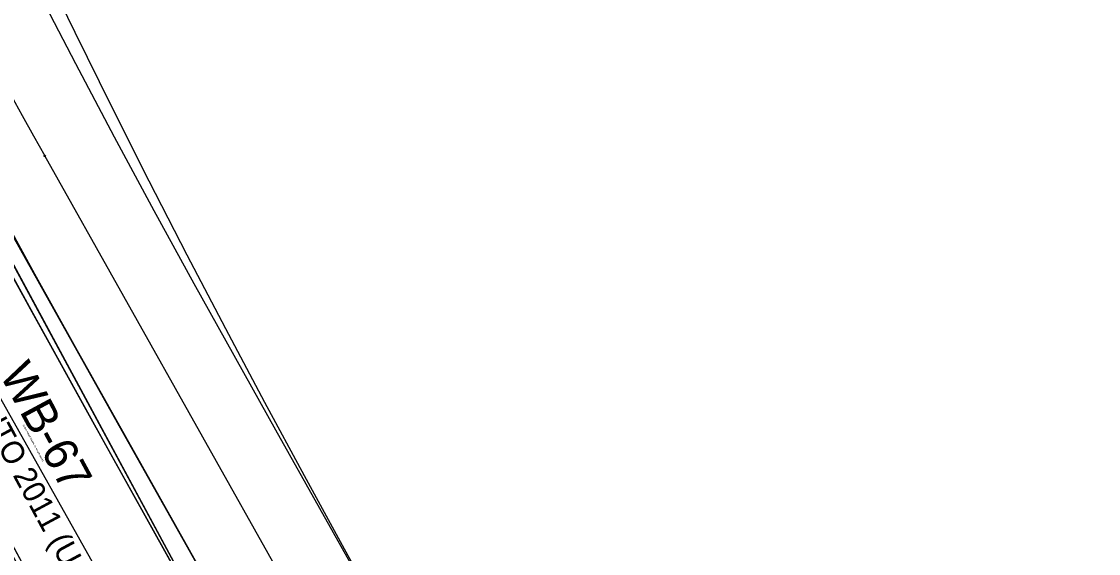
# Model space of a CAD drawing. Extents: x 1639988 to 1641860, y 841974 to 844187.
# Drawn here: x 1640568.3 to 1640636.6, y 843404.6 to 843438.4 of the extents above; entities that cross this region are included whole.
import ezdxf

# ---------------------------------------------------------------- set-up
doc = ezdxf.new("R2010")
doc.units = 0
for name, color, linetype in [('Scratch_Level_1', 7, 'Continuous'), ('Scratch_Level_2', 7, 'Continuous'), ('Scratch_Level_3', 7, 'Continuous'), ('Scratch_Level_4', 7, 'Continuous'), ('Scratch_Level_5', 7, 'Continuous'), ('Scratch_Level_6', 7, 'Continuous')]:
    doc.layers.add(name, color=color, linetype=linetype)

msp = doc.modelspace()

# ---------------------------------------------------------------- linework, layer by layer
at = {"layer": 'Scratch_Level_1'}
for p, q in [((1640598.915, 843377.886), (1640569.74, 843429.881)), ((1640561.019, 843424.987), (1640589.875, 843373.561))]:
    msp.add_line(p, q, dxfattribs=at)
for points in [[(1640557.303, 843442.315), (1640585.531, 843389.964), (1640585.474, 843389.635), (1640595.318, 843372.019), (1640588.329, 843368.125), (1640578.269, 843386.026), (1640578.051, 843385.927), (1640567.623, 843404.617), (1640561.145, 843416.327), (1640558.494, 843420.979), (1640555.889, 843425.657), (1640554.452, 843428.305), (1640561.33, 843432.392), (1640554.136, 843428.893), (1640551.649, 843433.615), (1640549.228, 843438.375), (1640546.875, 843443.171)], [(1640569.35, 843442.491), (1640571.641, 843437.743), (1640573.976, 843433.013), (1640576.351, 843428.298), (1640578.765, 843423.598), (1640581.214, 843418.911), (1640583.696, 843414.235), (1640586.206, 843409.569), (1640588.742, 843404.91), (1640593.874, 843395.608), (1640599.062, 843386.314), (1640636.63, 843319.355), (1640629.218, 843315.196), (1640629.14, 843315.333), (1640629.14, 843315.333)], [(1640629.14, 843315.333), (1640571.712, 843417.686), (1640569.11, 843422.364), (1640566.534, 843427.059), (1640563.994, 843431.777), (1640560.226, 843438.882)], [(1640552.934, 843432.517), (1640552.915, 843432.507), (1640552.949, 843432.445), (1640555.639, 843427.457), (1640578.051, 843385.927), (1640581.791, 843387.945), (1640585.531, 843389.964), (1640563.12, 843431.494), (1640560.428, 843436.481), (1640560.394, 843436.543), (1640560.375, 843436.533)]]:
    msp.add_lwpolyline(points, dxfattribs=at)
msp.add_circle((1640569.74, 843429.881), 0.0417, dxfattribs=at)
msp.add_circle((1640569.74, 843429.881), 0.0417, dxfattribs=at)
msp.add_arc((1640914.217, 843623.17), 395, 195.7144, 209.29724, dxfattribs=at)
at = {"layer": 'Scratch_Level_2'}
for p, q in [((1640598.915, 843377.886), (1640569.74, 843429.881)), ((1640561.019, 843424.987), (1640589.875, 843373.561))]:
    msp.add_line(p, q, dxfattribs=at)
for points in [[(1640557.951, 843441.151), (1640585.531, 843389.961), (1640585.474, 843389.635), (1640595.318, 843372.019), (1640588.329, 843368.125), (1640578.268, 843386.026), (1640578.049, 843385.928), (1640567.621, 843404.618), (1640561.144, 843416.329), (1640558.493, 843420.981), (1640555.888, 843425.659), (1640554.451, 843428.306), (1640561.331, 843432.39), (1640554.135, 843428.895), (1640551.648, 843433.617), (1640549.227, 843438.377), (1640546.874, 843443.173)], [(1640569.35, 843442.491), (1640571.641, 843437.743), (1640573.976, 843433.013), (1640576.351, 843428.298), (1640578.765, 843423.598), (1640581.214, 843418.911), (1640583.696, 843414.235), (1640586.206, 843409.569), (1640588.742, 843404.91), (1640593.874, 843395.608), (1640599.062, 843386.314), (1640636.63, 843319.355), (1640629.218, 843315.196), (1640629.144, 843315.327), (1640629.144, 843315.327)], [(1640629.144, 843315.327), (1640571.712, 843417.686), (1640569.11, 843422.364), (1640566.534, 843427.059), (1640563.994, 843431.777), (1640560.226, 843438.882)], [(1640552.951, 843432.529), (1640552.932, 843432.518), (1640552.966, 843432.456), (1640555.654, 843427.467), (1640578.049, 843385.928), (1640581.79, 843387.945), (1640585.531, 843389.961), (1640563.136, 843431.501), (1640560.446, 843436.489), (1640560.413, 843436.551), (1640560.394, 843436.541)]]:
    msp.add_lwpolyline(points, dxfattribs=at)
msp.add_circle((1640569.74, 843429.881), 0.0417, dxfattribs=at)
msp.add_circle((1640569.74, 843429.881), 0.0417, dxfattribs=at)
msp.add_arc((1640914.217, 843623.17), 395, 195.7144, 209.29724, dxfattribs=at)
at = {"layer": 'Scratch_Level_3'}
for p, q in [((1640598.915, 843377.886), (1640569.74, 843429.881)), ((1640561.019, 843424.987), (1640589.875, 843373.561))]:
    msp.add_line(p, q, dxfattribs=at)
for points in [[(1640556.856, 843443.205), (1640561.886, 843433.823), (1640585.531, 843389.961), (1640585.474, 843389.635), (1640595.318, 843372.019), (1640588.331, 843368.123), (1640578.268, 843386.026), (1640578.049, 843385.928), (1640567.621, 843404.618), (1640561.144, 843416.329), (1640558.493, 843420.981), (1640555.888, 843425.659), (1640554.451, 843428.306), (1640561.331, 843432.39), (1640554.135, 843428.895), (1640551.648, 843433.617), (1640549.227, 843438.377), (1640546.874, 843443.174)], [(1640569.35, 843442.491), (1640571.641, 843437.743), (1640573.976, 843433.013), (1640576.351, 843428.298), (1640578.765, 843423.598), (1640581.214, 843418.911), (1640583.696, 843414.235), (1640586.206, 843409.569), (1640588.742, 843404.91), (1640593.874, 843395.608), (1640599.062, 843386.314), (1640636.63, 843319.355), (1640629.218, 843315.196), (1640629.149, 843315.318), (1640629.149, 843315.318)], [(1640629.149, 843315.318), (1640571.712, 843417.686), (1640569.11, 843422.364), (1640566.534, 843427.059), (1640563.994, 843431.777), (1640560.226, 843438.882)], [(1640552.953, 843432.529), (1640552.933, 843432.519), (1640552.967, 843432.457), (1640555.656, 843427.468), (1640578.049, 843385.928), (1640581.79, 843387.945), (1640585.531, 843389.961), (1640563.138, 843431.501), (1640560.448, 843436.49), (1640560.414, 843436.552), (1640560.395, 843436.542)]]:
    msp.add_lwpolyline(points, dxfattribs=at)
msp.add_circle((1640569.74, 843429.881), 0.0417, dxfattribs=at)
msp.add_circle((1640569.74, 843429.881), 0.0417, dxfattribs=at)
msp.add_arc((1640914.217, 843623.17), 395, 195.7144, 209.29724, dxfattribs=at)
at = {"layer": 'Scratch_Level_4'}
for p, q in [((1640598.915, 843377.886), (1640569.74, 843429.881)), ((1640561.019, 843424.987), (1640589.875, 843373.561))]:
    msp.add_line(p, q, dxfattribs=at)
for points in [[(1640558.794, 843438.559), (1640563.861, 843429.211), (1640568.98, 843419.88), (1640574.133, 843410.56), (1640596.995, 843369.516), (1640589.571, 843365.377), (1640573.868, 843393.261), (1640581.129, 843397.688), (1640573.54, 843393.841), (1640559.056, 843419.365), (1640557.759, 843421.699), (1640556.481, 843424.044), (1640555.22, 843426.399), (1640553.978, 843428.764), (1640544.238, 843447.821)], [(1640611.208, 843347.292), (1640590.328, 843384.504), (1640574.652, 843412.392), (1640569.434, 843421.74), (1640561.561, 843435.788), (1640560.271, 843438.147), (1640559.001, 843440.517)], [(1640569.265, 843440.462), (1640571.686, 843435.764), (1640574.153, 843431.085), (1640576.662, 843426.421), (1640579.206, 843421.768), (1640584.378, 843412.479), (1640618.769, 843351.186), (1640611.357, 843347.027), (1640611.208, 843347.292), (1640611.208, 843347.292)]]:
    msp.add_lwpolyline(points, dxfattribs=at)
msp.add_circle((1640569.74, 843429.881), 0.0417, dxfattribs=at)
msp.add_circle((1640569.74, 843429.881), 0.0417, dxfattribs=at)
msp.add_arc((1640914.217, 843623.17), 395, 195.7144, 209.29724, dxfattribs=at)
at = {"layer": 'Scratch_Level_5'}
for p, q in [((1640598.915, 843377.886), (1640569.74, 843429.881)), ((1640561.019, 843424.987), (1640589.875, 843373.561))]:
    msp.add_line(p, q, dxfattribs=at)
for points in [[(1640558.636, 843438.852), (1640563.702, 843429.503), (1640568.819, 843420.171), (1640573.971, 843410.851), (1640596.995, 843369.516), (1640589.571, 843365.377), (1640573.868, 843393.261), (1640581.129, 843397.688), (1640573.54, 843393.841), (1640559.056, 843419.365), (1640557.759, 843421.699), (1640556.481, 843424.044), (1640555.22, 843426.399), (1640553.978, 843428.764), (1640544.238, 843447.821)], [(1640611.214, 843347.281), (1640590.328, 843384.504), (1640574.652, 843412.392), (1640569.434, 843421.74), (1640561.561, 843435.788), (1640560.271, 843438.147), (1640559.001, 843440.517)], [(1640569.265, 843440.462), (1640571.686, 843435.764), (1640574.153, 843431.085), (1640576.662, 843426.421), (1640579.206, 843421.768), (1640584.378, 843412.479), (1640618.769, 843351.186), (1640611.357, 843347.027), (1640611.214, 843347.281), (1640611.214, 843347.281)]]:
    msp.add_lwpolyline(points, dxfattribs=at)
msp.add_circle((1640569.74, 843429.881), 0.0417, dxfattribs=at)
msp.add_circle((1640569.74, 843429.881), 0.0417, dxfattribs=at)
msp.add_arc((1640914.217, 843623.17), 395, 195.7144, 209.29724, dxfattribs=at)
at = {"layer": 'Scratch_Level_6'}
for p, q in [((1640598.915, 843377.886), (1640569.74, 843429.881)), ((1640561.019, 843424.987), (1640589.875, 843373.561))]:
    msp.add_line(p, q, dxfattribs=at)
for points in [[(1640557.068, 843441.778), (1640562.112, 843432.422), (1640567.216, 843423.086), (1640572.358, 843413.763), (1640582.875, 843394.846), (1640596.995, 843369.516), (1640589.571, 843365.377), (1640573.868, 843393.261), (1640581.129, 843397.688), (1640573.54, 843393.841), (1640559.056, 843419.365), (1640557.759, 843421.699), (1640556.481, 843424.044), (1640555.22, 843426.399), (1640553.978, 843428.764), (1640544.238, 843447.821)], [(1640611.238, 843347.239), (1640590.328, 843384.504), (1640574.652, 843412.392), (1640569.434, 843421.74), (1640561.561, 843435.788), (1640560.271, 843438.147), (1640559.001, 843440.517)], [(1640569.265, 843440.462), (1640571.686, 843435.764), (1640574.153, 843431.085), (1640576.662, 843426.421), (1640579.206, 843421.768), (1640584.378, 843412.479), (1640618.769, 843351.186), (1640611.357, 843347.027), (1640611.238, 843347.239), (1640611.238, 843347.239)]]:
    msp.add_lwpolyline(points, dxfattribs=at)
msp.add_circle((1640569.74, 843429.881), 0.0417, dxfattribs=at)
msp.add_circle((1640569.74, 843429.881), 0.0417, dxfattribs=at)
msp.add_arc((1640914.217, 843623.17), 395, 195.7144, 209.29724, dxfattribs=at)

# ---------------------------------------------------------------- texts
at = {"layer": 'Scratch_Level_1'}
for s, height, p in [('AASHTO 2011 (US)', 1.41667, (1640563.738, 843416.91)), ('WB-67', 2.125, (1640566.833, 843416.022)), ('(c) 2019 Transoft Solutions, Inc. All rights reserved.', 0.085, (1640568.346, 843412.771))]:
    msp.add_text(s, height=height, rotation=298.35288, dxfattribs=at).set_placement(p)
at = {"layer": 'Scratch_Level_2'}
for s, height, p in [('AASHTO 2011 (US)', 1.41667, (1640563.748, 843416.917)), ('WB-67', 2.125, (1640566.843, 843416.028)), ('(c) 2019 Transoft Solutions, Inc. All rights reserved.', 0.085, (1640568.355, 843412.775))]:
    msp.add_text(s, height=height, rotation=298.32975, dxfattribs=at).set_placement(p)
at = {"layer": 'Scratch_Level_3'}
for s, height, p in [('AASHTO 2011 (US)', 1.41667, (1640563.749, 843416.918)), ('WB-67', 2.125, (1640566.844, 843416.028)), ('(c) 2019 Transoft Solutions, Inc. All rights reserved.', 0.085, (1640568.356, 843412.776))]:
    msp.add_text(s, height=height, rotation=298.32785, dxfattribs=at).set_placement(p)

doc.saveas('drawing.dxf')
